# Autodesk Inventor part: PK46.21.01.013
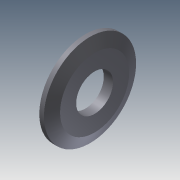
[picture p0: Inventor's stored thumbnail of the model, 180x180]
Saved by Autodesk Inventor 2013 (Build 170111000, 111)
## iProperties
Created: 2005-04
Part Number: PK46.21.01.013
Material: Steel, Mild
Document SubType Name: Modeling
Designer: salex
Manufacturer: Standard
Standards Organization: Custom
Density: 7.86 g/cm^3
Author: salex
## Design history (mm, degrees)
sketch "Эскиз1"
  geometry: L1 (0, 0)-(60.273, 0); L2 (0, 100)-(0, 40); L3 (0, 40)-(20, 40); L4 (20, 40)-(20, 75); L5 (20, 75)-(10, 100); L6 (10, 100)-(0, 100)
  constraints: 12 end point, 2 parallel, 2 perpendicular, 1 horizontal, 1 other
  dimensions: "d0" = 0 distance from line of L1.start L2; "d1" = 20 distance of L2.end L3.end; "d2" = 10 distance of L5.end L2.start; "d3" = 80 diameter of L3 L1; "d4" = 200 diameter of L6 L1; "d5" = 150 diameter of L4.end L1
revolve "Вращение1" sketch "Эскиз1" stored, may be unused: angle "d6" = 90 deg
body "Solid1"
